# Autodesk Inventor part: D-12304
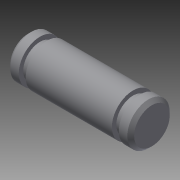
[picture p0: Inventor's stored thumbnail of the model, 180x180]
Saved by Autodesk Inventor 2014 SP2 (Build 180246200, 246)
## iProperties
Created: 2020-01
Part Number: D-12304
Material: Generic
Catalog Web Link: www.cadenas.de
Description: Piston Rod Clevis for Original Line Cylinders - Pin-
Vendor: BIMBA
Document SubType Name: Modeling
Designer: psadmin
Manufacturer: BIMBA
Mass: 0.233427 g
Surface Area: 2.57002 cm^2
Volume: 0.233427 cm^3
Density: 1 g/cm^3
Appearance: PSOLRGB-191-191-191
Category: PARTsolutions
Company: BIMBA
Title: D-12304
Author: Cadenas PARTsolutions
PSOL_IDENT_0: {$CADENAS_DATA\23d-libs\bimba\bimba_brand\bimba_imperial\bimba_full_line\original_line_cylinders\acc
PSOL_IDENT_1: essories\piston_rod_clevis_pin.prj},199 {VTYP=3D},{NB=D-12304},{LINA=D-12304},{NN=Piston Rod Clevis
PSOL_IDENT_2: for Original Line Cylinders - Pin},{DATE=23.12.2019 10:36:51},{GEOMDATE=03.04.2013 12:23:00},{VERSIO
PSOL_IDENT_3: N=},{LINEID=20},{WBVAR=},{WBNUMERIC=}  {NB=D-12304},{LINA=D-12304},{KT=DUMMY},{PN=D-12304},{L=0.5460
PSOL_IDENT_4: 0000},{L1=0.38000000},{L2=0.03050000},{L4=0.05250000},{D=0.18700000},{D1=0.14800000},{CH=0.01500000}
PSOL_IDENT_5: ,{R=0.00250000},{COLOR=0.75,0.75,0.75,0.00}
NN: Piston Rod Clevis for Original Line Cylinders - Pin
NB: D-12304
NBSYN: $PN.
LINA: D-12304
PN: D-12304
L: 0.546
L1: 0.38
L2: 0.0305
L4: 0.0525
D: 0.187
D1: 0.148
CH: 0.015
R: 0.0025
SUPPLIER: BIMBA
ARTICLENO: D-12304
BOMINFO: D-12304
CREATOR: CADENAS GmbH
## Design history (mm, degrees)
sketch "Sketch_1"
  geometry: L1 (6.934, 0)-(-6.934, 0); L2 (-6.934, 0)-(-6.934, 1.994); L3 (-6.934, 1.994)-(-6.553, 2.375); L4 (-6.553, 2.375)-(-5.601, 2.375); L5 (-5.601, 2.375)-(-5.601, 1.88); L6 (-5.601, 1.88)-(-4.826, 1.88); L7 (-4.826, 1.88)-(-4.826, 2.375); L8 (-4.826, 2.375)-(4.826, 2.375); L9 (4.826, 2.375)-(4.826, 1.88); L10 (4.826, 1.88)-(5.601, 1.88); L11 (5.601, 1.88)-(5.601, 2.375); L12 (5.601, 2.375)-(6.553, 2.375); L13 (6.553, 2.375)-(6.934, 1.994); L14 (6.934, 1.994)-(6.934, 0); L15 (6.934, 0)-(-6.934, 0)
  constraints: 30 end point
revolve "Revolution1" sketch "Sketch_1" stored, may be unused: angle "d0" = 360 deg
node "p1_XY"
node "p1_YZ"
node "p1_ZX"
node "p1_X"
node "p1_Y"
node "p1_Z"
node "p1_Center"
node "p2_XY"
node "p2_YZ"
node "p2_ZX"
node "p2_X"
node "p2_Y"
node "p2_Z"
node "p2_Center"
node "pin_XY"
node "pin_YZ"
node "pin_ZX"
node "pin_X"
node "pin_Y"
node "pin_Z"
node "pin_Center"
node "rr1_XY"
node "rr1_YZ"
node "rr1_ZX"
node "rr1_X"
node "rr1_Y"
node "rr1_Z"
node "rr1_Center"
node "rr2_XY"
node "rr2_YZ"
node "rr2_ZX"
node "rr2_X"
node "rr2_Y"
node "rr2_Z"
node "rr2_Center"
node "w21_XY"
node "w21_YZ"
node "w21_ZX"
node "w21_X"
node "w21_Y"
node "w21_Z"
node "w21_Center"
node "w22_XY"
node "w22_YZ"
node "w22_ZX"
node "w22_X"
node "w22_Y"
node "w22_Z"
node "w22_Center"
body "Solid1"
